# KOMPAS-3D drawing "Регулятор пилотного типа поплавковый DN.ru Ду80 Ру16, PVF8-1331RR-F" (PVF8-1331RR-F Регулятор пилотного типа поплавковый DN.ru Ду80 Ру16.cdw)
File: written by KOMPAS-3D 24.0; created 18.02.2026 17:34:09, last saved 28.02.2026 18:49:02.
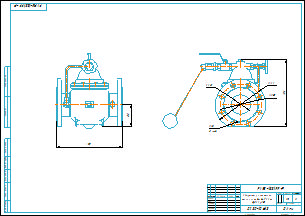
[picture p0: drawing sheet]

Document properties: art: D230-10613; Автор: R2D2; Форматы листов документа: A2; Полное имя файла: PVF8-1331RR-F Регулятор пилотного типа поплавковый DN.ru Ду80 Ру16.m3d; Масса: 13; Наименование: Регулятор пилотного типа поплавковый DN.ru Ду80 Ру16; Количество листов документа: 1; Примечание: D230-10613

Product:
- Part/product: Регулятор пилотного типа поплавковый DN.ru Ду80 Ру16  | designation PVF8-1331RR-F
    Масса: 13
    Раздел спецификации: Прочие изделия
    Примечание: D230-10613
    additional columns: D230-10613

Referenced files in E:\Работа\Зайцев\Для компаса\: чертеж DN.ru А3.cdt
Referenced files in E:\Работа\Зайцев\PVF8-1331RR-F Регулятор пилотного типа поплавковый DN.ru Ду15-300\DN80\: PVF8-1331RR-F Регулятор пилотного типа поплавковый DN.ru Ду80 Ру16.m3d
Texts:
  чертеж DN.ru А3.cdt
  Регулятор пилотного
  типа поплавковый DN.ru
  Ду80 Ру16
  PVF8-1331RR-F
  prop
  Регулятор пилотного типа поплавковый DN.ru Ду80 Ру16
  PVF8-1331RR-F Регулятор пилотного типа поплавковый DN.ru Ду80 Ру16
Dimensions and other numbers on the sheet: 1:2; 0; 1; 2; 13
